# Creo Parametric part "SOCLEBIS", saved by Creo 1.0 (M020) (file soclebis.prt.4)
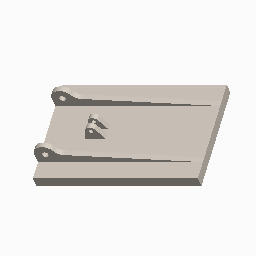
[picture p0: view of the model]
Units: Meter Kilogram Second (MKS); M, KILOGRAM, SECS
Materials in the file: FE20

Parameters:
  PTC_MATERIAL_NAME = "FE20"

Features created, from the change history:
  datum axis "A_1"
  datum axis "A_2"
  datum axis "A_3"

Other named items: SOCLEBIS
